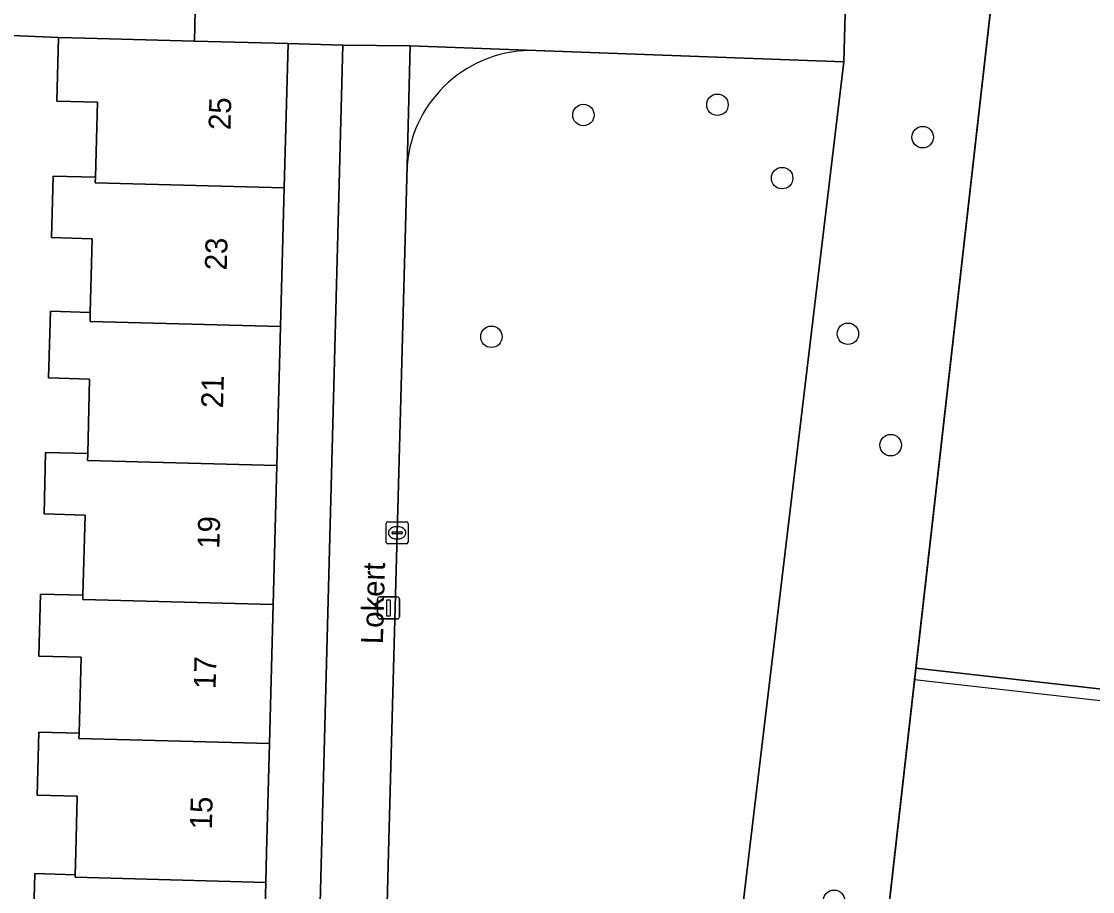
# Model space of a CAD drawing. Extents: x 162082 to 163401, y 388089 to 388636.
# Drawn here: x 162561.73 to 162610.54, y 388248.21 to 388287.84 of the extents above; entities that cross this region are included whole.
import ezdxf

# ---------------------------------------------------------------- set-up
doc = ezdxf.new("R2010")
doc.units = 0
for name, color, linetype in [('IMGEO_Boom', 7, 'Continuous'), ('IMGEO_Erf', 7, 'Continuous'), ('IMGEO_Groenvoorziening', 7, 'Continuous'), ('IMGEO_Hek', 7, 'Continuous'), ('IMGEO_Kolk', 7, 'Continuous'), ('IMGEO_Lichtmast', 7, 'Continuous'), ('IMGEO_Openbare_ruimte_label', 7, 'Continuous'), ('IMGEO_Pand', 7, 'Continuous'), ('IMGEO_Pand_nummerreeks', 7, 'Continuous'), ('IMGEO_Voetpad_open', 7, 'Continuous')]:
    doc.layers.add(name, color=color, linetype=linetype)

msp = doc.modelspace()

# ---------------------------------------------------------------- linework, layer by layer
at = {"layer": 'IMGEO_Boom'}
for centre in [(162593.446, 388284.049), (162587.34, 388283.581), (162602.798, 388282.573), (162596.392, 388280.707), (162599.389, 388273.619), (162583.148, 388273.481), (162601.338, 388268.546), (162598.759, 388247.794)]:
    msp.add_circle(centre, 0.489, dxfattribs=at)
at = {"layer": 'IMGEO_Erf'}
for points in [[(162612.925, 388350.456), (162602.483, 388258.384), (162656.21, 388252.334)], [(162562.276, 388246.261), (162562.35, 388249.03), (162564.183, 388248.981), (162564.21, 388250), (162564.278, 388252.563), (162562.452, 388252.612), (162562.528, 388255.48), (162564.362, 388255.431), (162564.454, 388258.888), (162562.535, 388258.939), (162562.61, 388261.758), (162564.536, 388261.707), (162564.633, 388265.361), (162562.763, 388265.411), (162562.838, 388268.21), (162564.753, 388268.159), (162564.843, 388271.556), (162562.972, 388271.606), (162563.053, 388274.643), (162564.87, 388274.595), (162564.96, 388277.949), (162563.102, 388277.998), (162563.177, 388280.803), (162565.102, 388280.752), (162565.193, 388284.17), (162563.353, 388284.219), (162563.431, 388287.118), (162558.479, 388287.33)], [(162573.067, 388202.528), (162573.993, 388235.663), (162575.021, 388235.649), (162575.403, 388250), (162576.383, 388286.759), (162573.884, 388286.839), (162573.709, 388280.271), (162573.541, 388273.943), (162573.372, 388267.615), (162573.204, 388261.288), (162573.035, 388254.96), (162572.903, 388250), (162572.867, 388248.632), (162572.698, 388242.304), (162572.523, 388235.734), (162567.525, 388235.867), (162563.878, 388235.964), (162563.981, 388239.835), (162562.106, 388239.885), (162562.186, 388242.878), (162564.018, 388242.829), (162564.108, 388246.212)]]:
    msp.add_lwpolyline(points, dxfattribs=at)
at = {"layer": 'IMGEO_Groenvoorziening'}
for points in [[(162612.925, 388350.456), (162613.478, 388355.34), (162601.206, 388356.658), (162601.036, 388350.695), (162604.215, 388350.105), (162605.076, 388349.881), (162606.015, 388349.429), (162606.444, 388349.132), (162607.197, 388348.412), (162607.784, 388347.552), (162608.18, 388346.588), (162608.3, 388346.08), (162608.378, 388345.041), (162603.983, 388301.92), (162599.649, 388301.909), (162599.197, 388286.008), (162594.898, 388250), (162593.656, 388239.599), (162591.012, 388235.568), (162589.738, 388194.638), (162594.952, 388194.486), (162595.615, 388202.972), (162596.208, 388203.054), (162602.483, 388258.384)], [(162708.484, 388229.124), (162656.335, 388234.801), (162656.279, 388234.387), (162663.577, 388233.565), (162659.497, 388198.553), (162635.737, 388200.74), (162640.847, 388243.608), (162655.066, 388242.035), (162655.191, 388243.088), (162656.169, 388251.807), (162656.21, 388252.334), (162602.483, 388258.384), (162596.208, 388203.054), (162600.069, 388202.629), (162612.235, 388201.026), (162637.2, 388198.38), (162662.426, 388195.481), (162666.371, 388195.051), (162704.239, 388190.913), (162708.41, 388228.518)]]:
    msp.add_lwpolyline(points, close=True, dxfattribs=at)
msp.add_lwpolyline([(162579.307, 388281.284), (162578.466, 388250), (162578.092, 388235.955), (162591.012, 388235.568), (162593.656, 388239.599), (162594.898, 388250), (162599.197, 388286.008), (162585.177, 388286.522)], dxfattribs=at)
msp.add_arc((162584.993, 388280.82), 5.705, 88.1508, 175.3364, dxfattribs=at)
at = {"layer": 'IMGEO_Hek'}
for points in [[(162612.925, 388350.456), (162596.208, 388203.054)], [(162602.425, 388257.867), (162656.169, 388251.807)]]:
    msp.add_lwpolyline(points, dxfattribs=at)
at = {"layer": 'IMGEO_Kolk'}
for p, q in [((162578.352, 388264.127), (162578.352, 388264.979)), ((162578.427, 388265.053), (162579.279, 388265.053)), ((162578.84, 388264.833), (162578.865, 388264.833)), ((162579.353, 388264.979), (162579.353, 388264.127)), ((162578.611, 388264.547), (162578.611, 388264.559)), ((162579.049, 388264.51), (162578.651, 388264.51)), ((162578.654, 388264.596), (162579.052, 388264.596)), ((162578.863, 388264.273), (162578.838, 388264.273)), ((162579.095, 388264.559), (162579.095, 388264.547)), ((162579.279, 388264.053), (162578.427, 388264.053))]:
    msp.add_line(p, q, dxfattribs=at)
for points in [[(162578.352, 388264.127), (162578.352, 388264.979)], [(162578.427, 388265.053), (162579.279, 388265.053)], [(162579.353, 388264.979), (162579.353, 388264.127)], [(162579.279, 388264.053), (162578.427, 388264.053)]]:
    msp.add_lwpolyline(points, dxfattribs=at)
for centre, radius, start, end in [((162578.429, 388264.977), 0.0765, 91.552, 178.448), ((162578.429, 388264.977), 0.0765, 91.552, 178.448), ((162579.277, 388264.977), 0.0765, 1.552, 88.448), ((162579.277, 388264.977), 0.0765, 1.552, 88.448), ((162578.651, 388264.556), 0.0403, 85.8775, 175.7526), ((162578.648, 388264.546), 0.0366, 178.938, 274.7102), ((162579.052, 388264.553), 0.043, 264.8664, 352.4533), ((162579.056, 388264.558), 0.0386, 1.7309, 96.639), ((162578.429, 388264.129), 0.0765, 181.552, 268.448), ((162578.429, 388264.129), 0.0765, 181.552, 268.448), ((162579.277, 388264.129), 0.0765, 271.552, 358.448), ((162579.277, 388264.129), 0.0765, 271.552, 358.448)]:
    msp.add_arc(centre, radius, start, end, dxfattribs=at)
for centre, major_axis, ratio, start_param, end_param in [((162578.839, 388264.553), (-0.387, 0.002), 0.722429, 4.712389, 7.853982), ((162578.864, 388264.553), (-0.39, 0.002), 0.717154, 1.570796, 4.712389)]:
    msp.add_ellipse(centre, major_axis=major_axis, ratio=ratio, start_param=start_param, end_param=end_param, dxfattribs=at)
at = {"layer": 'IMGEO_Lichtmast'}
for p, q in [((162577.963, 388260.731), (162577.963, 388261.531)), ((162577.963, 388261.531), (162577.963, 388260.731)), ((162578.063, 388261.631), (162578.853, 388261.631)), ((162578.853, 388261.631), (162578.063, 388261.631)), ((162578.953, 388261.531), (162578.953, 388260.731)), ((162578.953, 388260.731), (162578.953, 388261.531)), ((162578.853, 388260.631), (162578.063, 388260.631)), ((162578.063, 388260.631), (162578.853, 388260.631))]:
    msp.add_line(p, q, dxfattribs=at)
msp.add_lwpolyline([(162578.383, 388261.506), (162578.533, 388261.506), (162578.533, 388260.756), (162578.383, 388260.756), (162578.383, 388261.506)], dxfattribs=at)
for centre, start, end in [((162578.063, 388261.531), 90, 180), ((162578.063, 388261.531), 90, 180), ((162578.853, 388261.531), 0, 90), ((162578.853, 388261.531), 360, 90), ((162578.063, 388260.731), 180, 270), ((162578.063, 388260.731), 180, 270), ((162578.853, 388260.731), 270, 0), ((162578.853, 388260.731), 270, 0)]:
    msp.add_arc(centre, 0.1, start, end, dxfattribs=at)
at = {"layer": 'IMGEO_Pand'}
for points in [[(162573.709, 388280.271), (162573.884, 388286.839), (162569.617, 388286.953), (162564.619, 388287.087), (162563.431, 388287.118), (162563.353, 388284.219), (162565.193, 388284.17), (162565.102, 388280.752), (162565.095, 388280.5)], [(162573.541, 388273.943), (162573.709, 388280.271), (162565.095, 388280.5), (162565.102, 388280.752), (162563.177, 388280.803), (162563.102, 388277.998), (162564.96, 388277.949), (162564.87, 388274.595), (162564.859, 388274.174)], [(162564.753, 388268.159), (162564.745, 388267.844), (162573.372, 388267.615), (162573.541, 388273.943), (162564.859, 388274.174), (162564.87, 388274.595), (162563.053, 388274.643), (162562.972, 388271.606), (162564.843, 388271.556)], [(162564.753, 388268.159), (162562.838, 388268.21), (162562.763, 388265.411), (162564.633, 388265.361), (162564.536, 388261.707), (162564.531, 388261.518), (162573.204, 388261.288), (162573.372, 388267.615), (162564.745, 388267.844)], [(162564.362, 388255.431), (162564.356, 388255.19), (162573.035, 388254.96), (162573.204, 388261.288), (162564.531, 388261.518), (162564.536, 388261.707), (162562.61, 388261.758), (162562.535, 388258.939), (162564.454, 388258.888)], [(162564.362, 388255.431), (162562.528, 388255.48), (162562.452, 388252.612), (162564.278, 388252.563), (162564.21, 388250), (162564.183, 388248.981), (162564.18, 388248.863), (162572.867, 388248.632), (162572.903, 388250), (162573.035, 388254.96), (162564.356, 388255.19)], [(162564.018, 388242.829), (162564.01, 388242.535), (162572.698, 388242.304), (162572.867, 388248.632), (162564.18, 388248.863), (162564.183, 388248.981), (162562.35, 388249.03), (162562.276, 388246.261), (162564.108, 388246.212)]]:
    msp.add_lwpolyline(points, close=True, dxfattribs=at)
at = {"layer": 'IMGEO_Voetpad_open'}
for points in [[(162570.216, 388309.531), (162569.995, 388301.216), (162569.659, 388288.519), (162569.655, 388288.359), (162569.617, 388286.953), (162573.884, 388286.839), (162576.383, 388286.759), (162579.445, 388286.732), (162585.177, 388286.522), (162599.197, 388286.008), (162599.649, 388301.909), (162601.036, 388350.695), (162601.206, 388356.658), (162598.183, 388356.743), (162598.056, 388352.244), (162596.595, 388300.46), (162596.443, 388295.073), (162596.351, 388291.81), (162596.289, 388289.61), (162592.192, 388289.736)], [(162558.479, 388287.33), (162563.431, 388287.118), (162564.619, 388287.087), (162569.617, 388286.953), (162569.655, 388288.359), (162567.688, 388288.411), (162562.91, 388288.538), (162561.171, 388288.584)], [(162578.095, 388231.896), (162578.092, 388235.955), (162578.466, 388250), (162579.307, 388281.284), (162579.445, 388286.732), (162576.383, 388286.759), (162575.403, 388250), (162575.021, 388235.649), (162573.993, 388235.663), (162573.067, 388202.528)], [(162585.177, 388286.522), (162579.445, 388286.732), (162579.307, 388281.284)]]:
    msp.add_lwpolyline(points, dxfattribs=at)
msp.add_arc((162584.993, 388280.82), 5.705, 88.1508, 175.3364, dxfattribs=at)

# ---------------------------------------------------------------- texts
at = {"layer": 'IMGEO_Openbare_ruimte_label'}
msp.add_text('Lokert', height=1, rotation=88.4534, dxfattribs=at).set_placement((162578.203, 388259.472))
at = {"layer": 'IMGEO_Pand_nummerreeks'}
for s, p in [('25', (162571.258, 388282.886)), ('23', (162571.088, 388276.498)), ('21', (162570.921, 388270.222)), ('19', (162570.751, 388263.813)), ('17', (162570.58, 388257.425)), ('15', (162570.41, 388251.037))]:
    msp.add_text(s, height=1, rotation=88.4745, dxfattribs=at).set_placement(p)

doc.saveas('drawing.dxf')
